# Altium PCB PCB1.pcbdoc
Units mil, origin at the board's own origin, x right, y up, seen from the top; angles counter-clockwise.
Board outline 4960.63 x 4488.19 mil, 2 copper layers (Top Layer, Bottom Layer), stack 62.206 mil thick; 33 components, 44 nets, 173 pads, 61 vias.
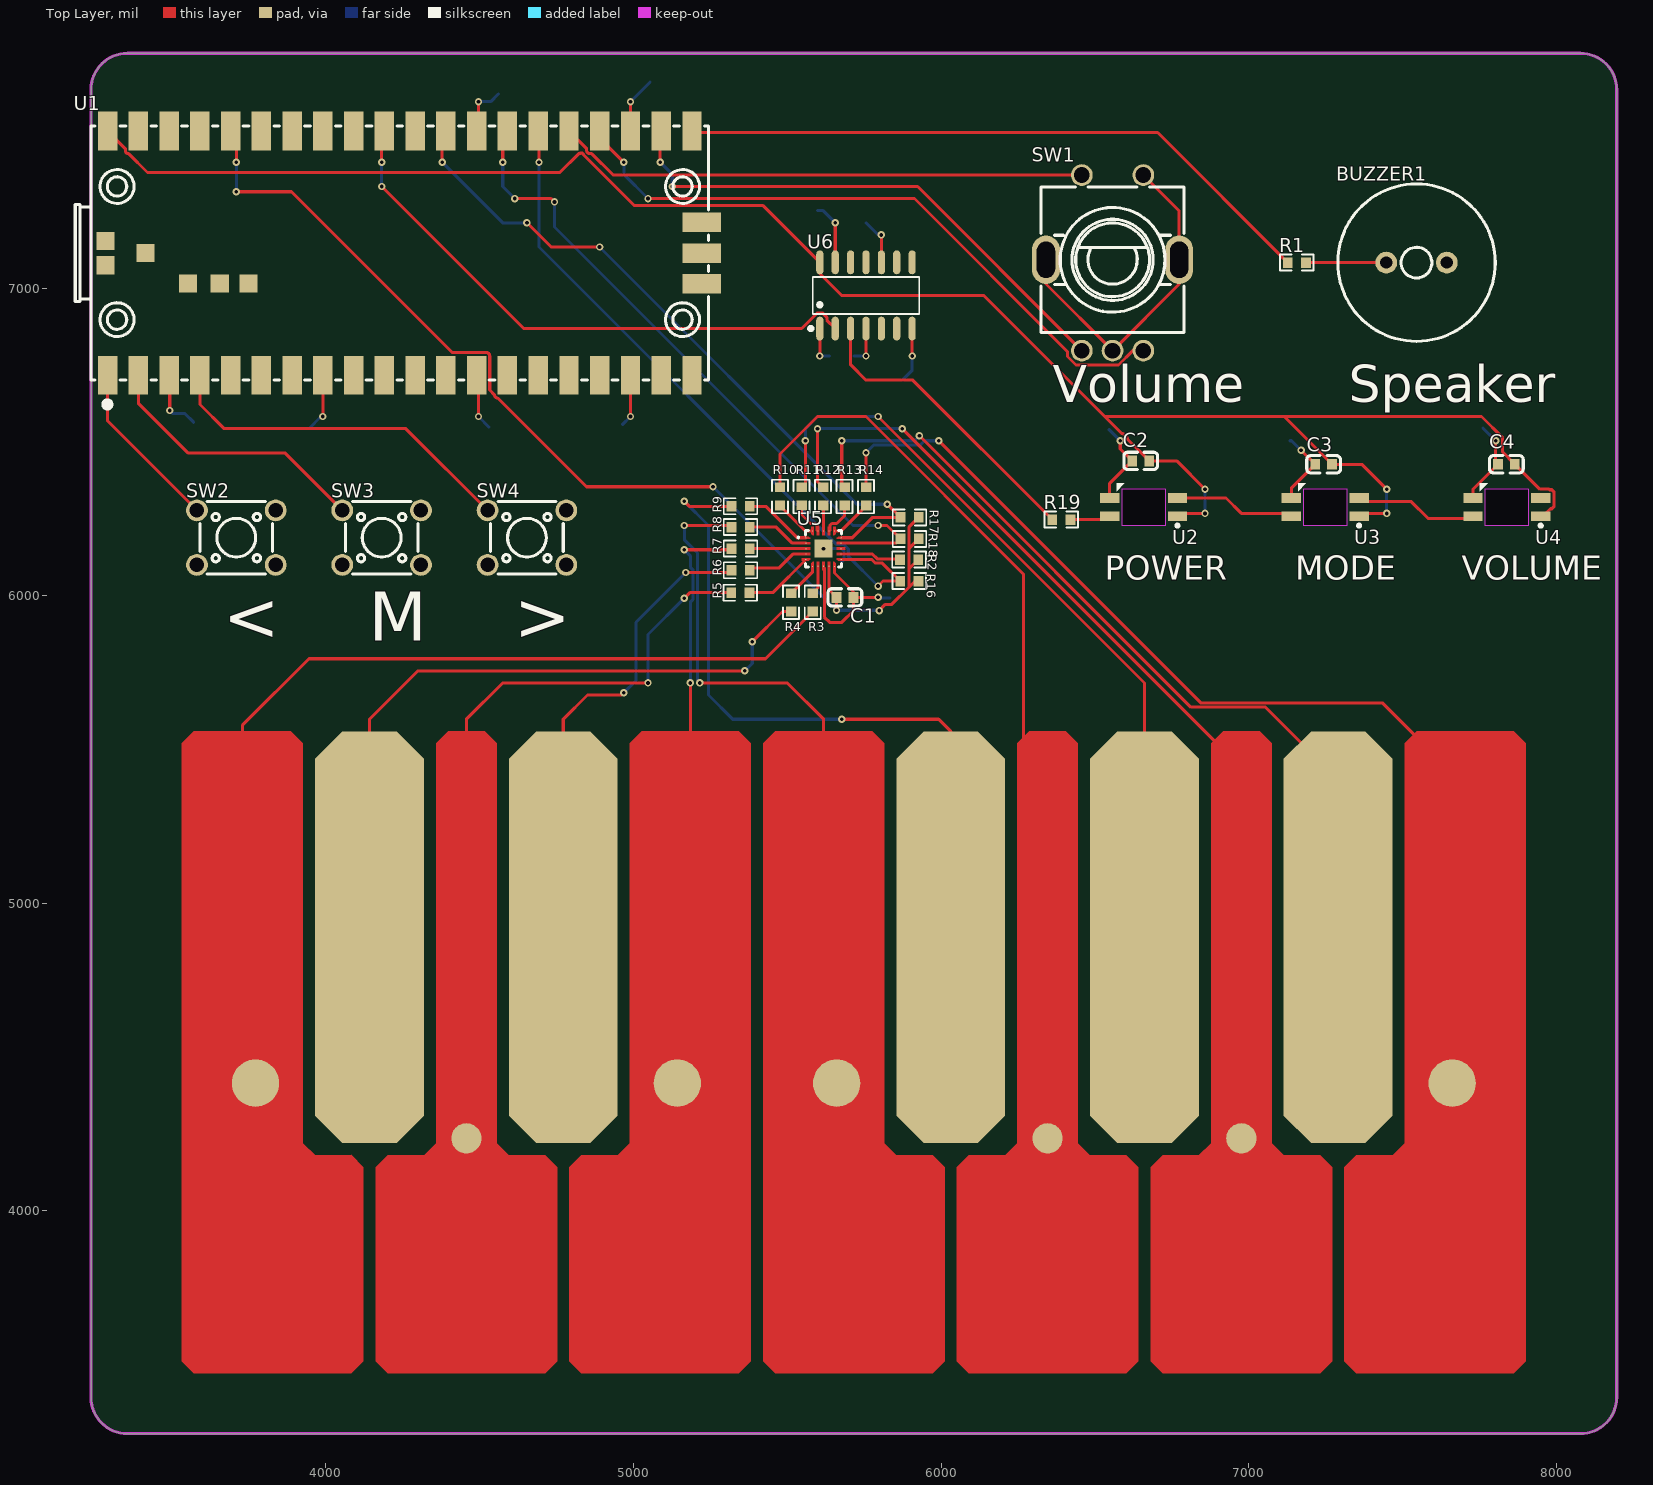
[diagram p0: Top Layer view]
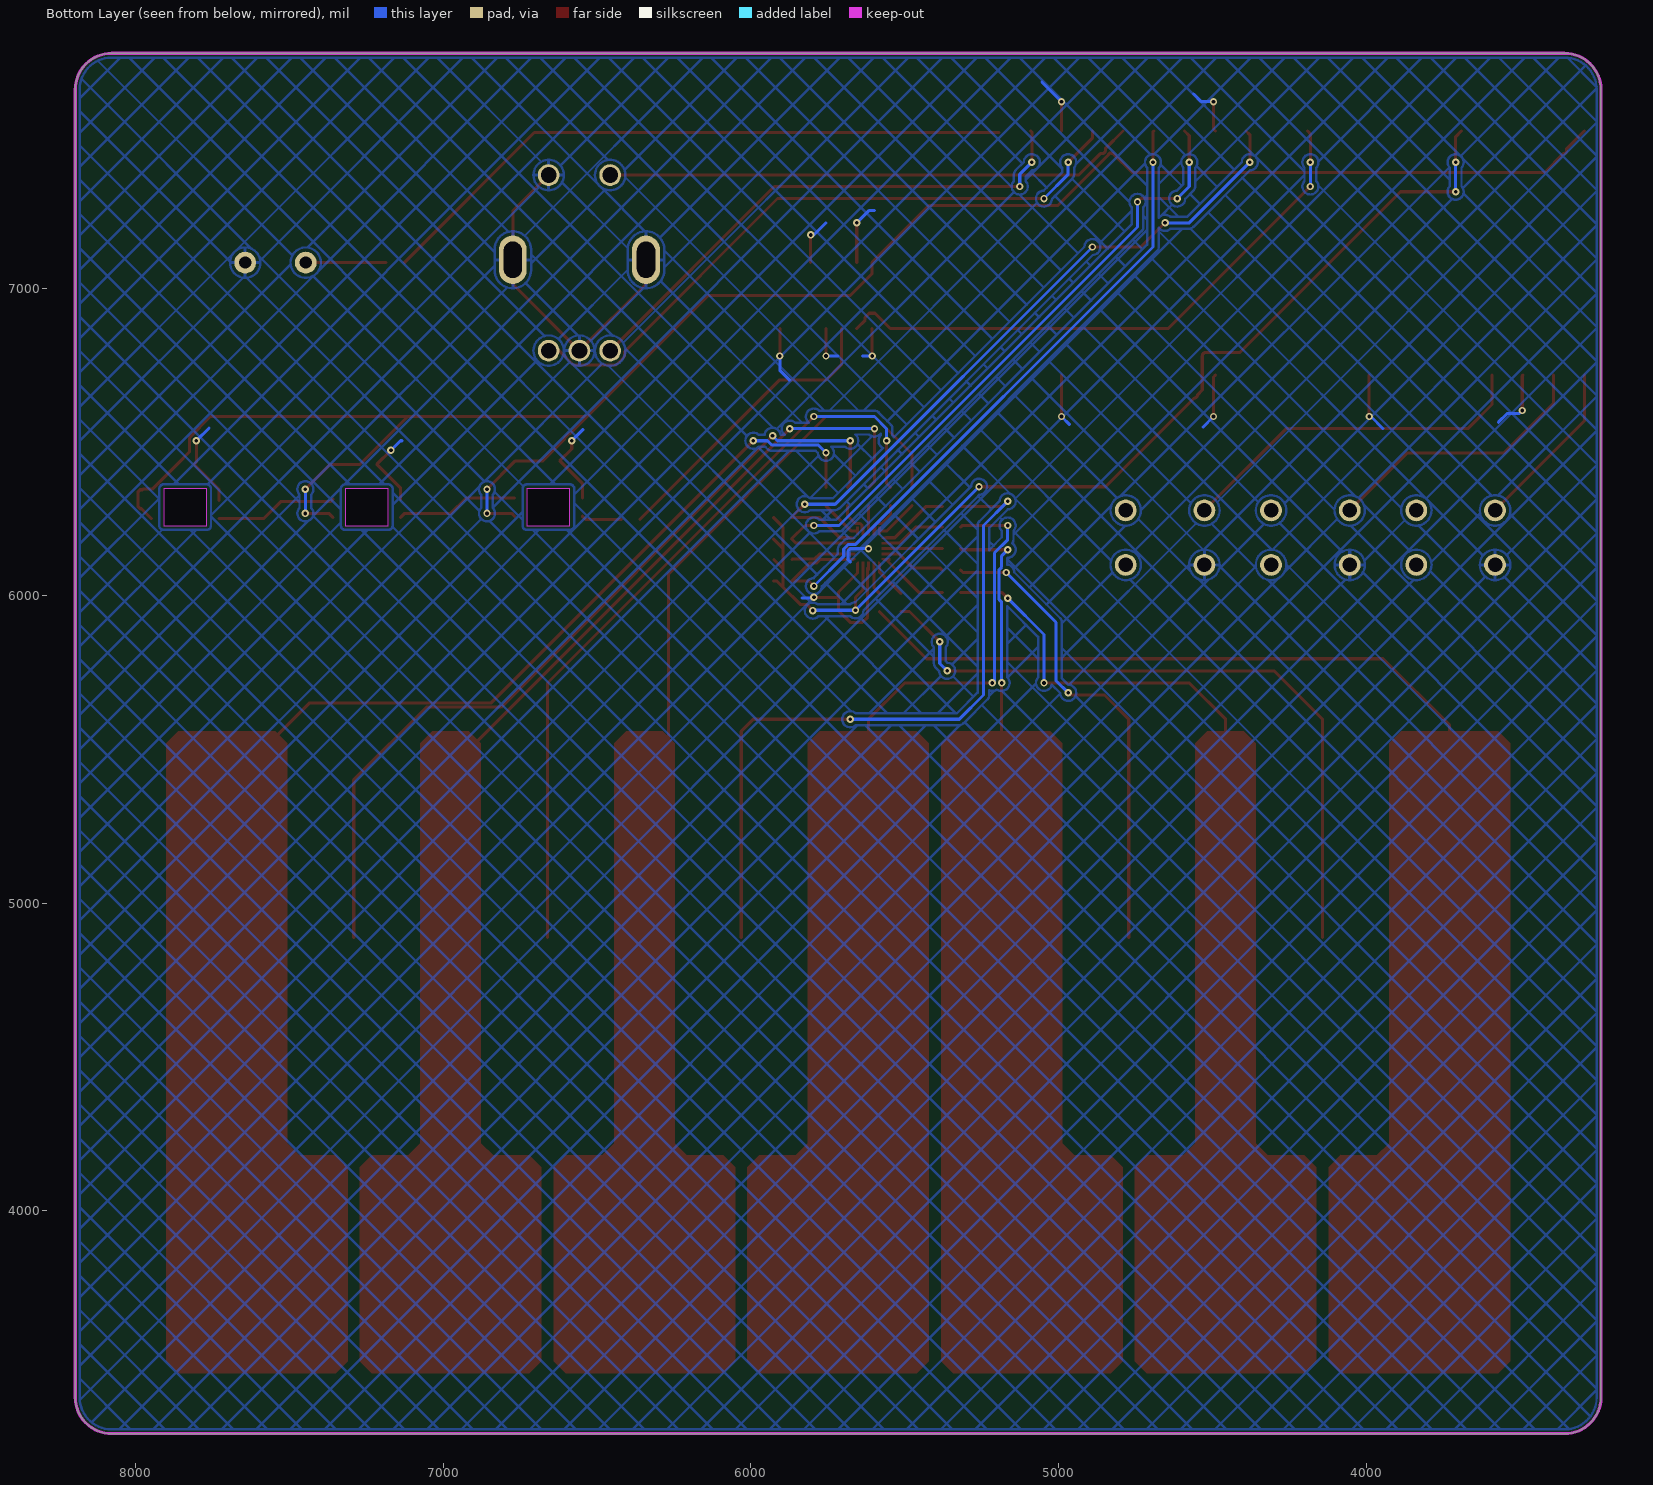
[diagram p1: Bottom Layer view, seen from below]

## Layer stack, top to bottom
Top Solder Mask Layer: solder mask 0.394, Dk 3.3
Top Layer: signal copper 1.379
Dielectric1: surface 59.449, FR4, Dk 4.5
Bottom Layer: signal copper 1.378
Bottom Solder Mask Layer: solder mask 0.394, Dk 3.3

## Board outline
3354.33,7763.78 ccw(c3354.33,7645.67) 3236.22,7645.67 3236.22,3393.7 ccw(c3354.33,3393.7) 3354.33,3275.59 8078.74,3275.59 ccw(c8078.74,3393.7) 8196.85,3393.7 8196.85,7645.67 ccw(c8078.74,7645.67) 8078.74,7763.78

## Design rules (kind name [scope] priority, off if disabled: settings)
BoardOutlineClearance copperThickness1oz [All] p0: genericclearance=10 ignorepadtopadclearanceinfootprint=FALSE except(0: Arc-SplitContinuation Track-SplitContinuation SMDPad-SplitContinuation THPad-SplitContinuation Via-SplitContinuation Fill-SplitContinuation Poly-SplitContinuation Region-SplitContinuation Text-SplitContinuation)
BoardOutlineClearance copperThickness2oz [All] p0: genericclearance=10 ignorepadtopadclearanceinfootprint=FALSE except(0: Arc-SplitContinuation Track-SplitContinuation SMDPad-SplitContinuation THPad-SplitContinuation Via-SplitContinuation Fill-SplitContinuation Poly-SplitContinuation Region-SplitContinuation Text-SplitContinuation)
BoardOutlineClearance otherClearance [All] p0: genericclearance=10 ignorepadtopadclearanceinfootprint=FALSE except(0: Arc-SplitContinuation Track-SplitContinuation SMDPad-SplitContinuation THPad-SplitContinuation Via-SplitContinuation Fill-SplitContinuation Poly-SplitContinuation Region-SplitContinuation Text-SplitContinuation)
Clearance copperThickness1oz [All] p1: gap=7 ignorepadtopadclearanceinfootprint=FALSE
Clearance copperThickness2oz [All] p1: gap=7 ignorepadtopadclearanceinfootprint=FALSE
Clearance otherClearance [All] p1: gap=7 ignorepadtopadclearanceinfootprint=FALSE
DiffPairsRouting differentialPair [All] p1: maxuncoupledlength=10 minlimit=6 maxlimit=Infinity mostfreqgap=6 toplayer_minwidth=5 toplayer_prefwidth=10 toplayer_maxwidth=100 bottomlayer_minwidth=5 bottomlayer_prefwidth=10 bottomlayer_maxwidth=100
PasteMaskExpansion pasteMaskExpansion [All] p1: expansion=0
PlaneConnect innerPlane [All] p1: planeconnectstyle=Relief reliefexpansion=20 reliefentries=4 reliefconductorwidth=10 reliefairgap=10
PolygonConnect copperRegion [All] p1: connectstyle=Relief reliefentries=4 reliefconductorwidth=10 polygonreliefangle="90 Angle" airgapwidth=10
RoutingVias viaSize [All] p1: viastyle="Through Hole" holewidth=12.0078 minholewidth=11.811 maxholewidth=248.0314 width=12.0078 minwidth=11.811 maxwidth=248.0314
SolderMaskExpansion solderMaskExpansion [IsVia] p1: useseparateexpansions=TRUE expansion=-1000 expansionbottom=-1000
SolderMaskExpansion solderMaskExpansion [All] p2: useseparateexpansions=TRUE expansion=2 expansionbottom=2
Width copperThickness1oz [All] p1: maxlimit=100 minlimit=5 preferedwidth=10
Width copperThickness2oz [All] p1: maxlimit=100 minlimit=8 preferedwidth=10

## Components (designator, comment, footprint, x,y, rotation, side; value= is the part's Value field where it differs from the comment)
BUZZER1 "4kHz" BUZ-TH_BD12.5-P5.00-D0.9 7545.92,7083.06 r0 top
C1 "100nF" C0603 5687.52,5994.88 r180 top
C2 "100nF" C0603 6648.98,6438.66 r180 top
C3 "100nF" C0603 7243.78,6427.4 r180 top
C4 "100nF" C0603 7838.16,6427.59 r180 top
R1 "220" R0603 7156.74,7083.06 r0 top
R2 "10K" R0603 5896.06,6117.7 r0 top
R3 "4.7K" R0603 5582.64,5978.44 r90 top
R4 "4.7K" R0603 5512.64,5978.44 r90 top
R5 "4.7K" R0603 5347.52,6009.88 r0 top
R6 "4.7K" R0603 5347.98,6083.1 r0 top
R7 "4.7K" R0603 5347.98,6153.1 r0 top
R8 "4.7K" R0603 5347.98,6223.1 r0 top
R9 "4.7K" R0603 5347.98,6290.8 r0 top
R10 "4.7K" R0603 5476.4,6322.76 r90 top
R11 "4.7K" R0603 5546.4,6322.76 r90 top
R12 "4.7K" R0603 5616.4,6322.76 r90 top
R13 "4.7K" R0603 5686.4,6322.76 r90 top
R14 "4.7K" R0603 5756.4,6322.76 r90 top
R16 "4.7K" R0603 5896.87,6047.7 r0 top
R17 "47K" R0603 5897.52,6254.88 r0 top
R18 "4.7K" R0603 5897.52,6184.88 r180 top
R19 "330" R0603 6390.97,6247.74 r0 top
SW1 "EC11E18244AU" SW-TH_EC11XXXXXXXX 6557.74,7082.33 r0 top
SW2 "1825910-6" SW-TH_4P-L6.0-W6.0-P4.50-LS6.5 3708.66,6188.98 r0 top
SW3 "1825910-6" SW-TH_4P-L6.0-W6.0-P4.50-LS6.5 4181.1,6188.98 r0 top
SW4 "1825910-6" SW-TH_4P-L6.0-W6.0-P4.50-LS6.5 4653.54,6188.98 r0 top
U1 "Raspberry Pi Pico 2" COMM-SMD_L51.0-W21.0-P2.54_SC0916 4252.55,7114.19 r0 top
U2 "IN-PI32TAR5R5G5B" LED-SMD_IN-PI32TARXRXGXB 6658.49,6288.06 r180 top
U3 "IN-PI32TAR5R5G5B" LED-SMD_IN-PI32TARXRXGXB 7249.04,6288.06 r180 top
U4 "IN-PI32TAR5R5G5B" LED-SMD_IN-PI32TARXRXGXB 7839.59,6288.06 r180 top
U5 "AT42QT2120-MMH" VQFN-20_L3.0-W3.0-P0.45-TL-EP 5617.88,6153.1 r0 top
U6 "74AHCT125D,118" SOP-14_L8.6-W3.9-P1.27-LS6.0-BL 5755.91,6976.38 r0 top

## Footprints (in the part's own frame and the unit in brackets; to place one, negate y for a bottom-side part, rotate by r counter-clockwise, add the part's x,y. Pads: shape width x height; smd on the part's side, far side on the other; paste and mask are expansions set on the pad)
BUZ-TH_BD12.5-P5.00-D0.9 [mm]
  round 1.8 hole 1: 1(-2.5,0) 2(2.5,0)
  silkscreen extent -6.5,-6.5 6.5,6.5
C0603 [mm]
  rect 0.8x0.9 smd: 1(-0.7,0) 2(0.7,0)
  silkscreen extent -1.39,-0.71 1.39,0.71
COMM-SMD_L51.0-W21.0-P2.54_SC0916 [mm]
  rect 1.6x3.2 smd: 1(-24.445,-10.087) 2(-21.905,-10.087) 3(-19.365,-10.087) 4(-16.825,-10.087) 5(-14.285,-10.087) 6(-11.745,-10.087) 7(-9.205,-10.087) 8(-6.665,-10.087) 9(-4.125,-10.087) 10(-1.585,-10.087) 11(0.955,-10.087) 12(3.495,-10.087) 13(6.035,-10.087) 14(8.575,-10.087) 15(11.115,-10.087) 16(13.655,-10.087) 17(16.195,-10.087) 18(18.735,-10.087) 19(21.275,-10.087) 20(23.815,-10.087) 21(23.815,10.087) 22(21.275,10.087) 23(18.735,10.087) 24(16.195,10.087) 25(13.655,10.087) 26(11.115,10.087) 27(8.575,10.087) 28(6.035,10.087) 29(3.495,10.087) 30(0.955,10.087) 31(-1.585,10.087) 32(-4.125,10.087) 33(-6.665,10.087) 34(-9.205,10.087) 35(-11.745,10.087) 36(-14.285,10.087) 37(-16.825,10.087) 38(-19.365,10.087) 39(-21.905,10.087) 40(-24.445,10.087)
  rect 3.2x1.6 smd: 41(24.615,-2.54) 42(24.615,0) 43(24.615,2.54)
  rect 1.5x1.5 smd: TP1(-21.315,0) TP2(-24.615,1) TP3(-24.615,-1) TP4(-17.815,-2.5) TP5(-15.188,-2.5) TP6(-12.815,-2.5)
  silkscreen extent -27.11,-12.75 25.18,10.5
LED-SMD_IN-PI32TARXRXGXB [mm]
  rect 1.6x0.82 smd: 1(-2.8,0.75) 2(-2.8,-0.75) 3(2.8,-0.75) 4(2.8,0.75)
  Board Outline Layer lines w0.003: 1.778,1.524 1.651,1.524 -1.651,1.524 -1.778,1.524 -1.778,-1.524 1.778,-1.524 1.778,1.524
  Board Outline Layer region: -1.651,1.524 1.651,1.524 1.778,1.524 1.778,-1.524 -1.778,-1.524 -1.778,1.524
  Board Outline Layer region: -1.651,1.524 1.651,1.524 1.778,1.524 1.778,-1.524 -1.778,-1.524 -1.778,1.524
  Multi-Layer board cut-out: -1.651,1.524 1.651,1.524 1.778,1.524 1.778,-1.524 -1.778,-1.524 -1.778,1.524
  silkscreen extent -2.92,-1.97 2.22,1.65
R0603 [mil]
  rect 31.75x34.02 smd paste-3937.01 mask+2: 1(-29.66,0) 2(29.66,0)
  silkscreen extent -55,-26 55,26
SOP-14_L8.6-W3.9-P1.27-LS6.0-BL [mm]
  oval 0.595x1.968 smd: 1(-3.81,-2.734) 2(-2.54,-2.734) 3(-1.27,-2.734) 4(0,-2.734) 5(1.27,-2.734) 6(2.54,-2.734) 7(3.81,-2.734) 8(3.81,2.734) 9(2.54,2.734) 10(1.27,2.734) 11(0,2.734) 12(-1.27,2.734) 13(-2.54,2.734) 14(-3.81,2.734)
  silkscreen extent -4.71,-2.88 4.4,1.52
SW-TH_4P-L6.0-W6.0-P4.50-LS6.5 [mm]
  round 1.8 hole 1.2: 1(-3.25,2.25) 2(3.25,2.25) 3(-3.25,-2.25) 4(3.25,-2.25)
  silkscreen extent -3,-3 3,3
SW-TH_EC11XXXXXXXX [mm]
  oval 2.3x4 hole 1.5 slot 3 at 90 deg: 6(5.5,0.25) 7(-5.5,0.25)
  round 1.8 hole 1.3: A(-2.54,-7.25) B(2.54,-7.25) C(0,-7.25) D(-2.54,7.25) E(2.54,7.25)
  silkscreen extent -5.9,-5.75 5.9,6.25
VQFN-20_L3.0-W3.0-P0.45-TL-EP [mm]
  round 0.098 smd: 1(-1.462,0.898) 5(-1.462,-0.898) 6(-0.898,-1.462) 11(1.462,-0.897) 16(0.898,1.462) 20(-0.898,1.462)
  round 0.1 smd: 2(-1.45,0.45) 3(-1.45,0) 4(-1.45,-0.45) 7(-0.45,-1.45) 8(0,-1.45) 9(0.45,-1.45) 12(1.45,-0.45) 13(1.45,0) 14(1.45,0.45) 17(0.45,1.45) 18(0,1.45) 19(-0.45,1.45)
  round 0.097 smd: 10(0.898,-1.462) 15(1.462,0.898)
  rect 1.5x1.5 smd paste-100 mask+0.05: 21(0,0)
  Top Layer region: 0.55,-1.7 0.55,-1.8 0.35,-1.8 0.35,-1.1 0.55,-1.1
  Top Layer region: -0.8,-1.1 -0.8,-1.8 -1,-1.8 -1,-1.25 -1,-1.2 -0.9,-1.1
  Top Layer region: -1.1,0.8 -1.8,0.8 -1.8,1 -1.25,1 -1.2,1 -1.1,0.9
  Top Layer region: 1.1,0.8 1.8,0.8 1.8,1 1.25,1 1.2,1 1.1,0.9
  Top Layer region: 0.8,1.1 0.8,1.8 1,1.8 1,1.25 1,1.2 0.9,1.1
  Top Layer region: 0.8,-1.1 0.8,-1.8 1,-1.8 1,-1.25 1,-1.2 0.9,-1.1
  Top Layer region: 1.1,-0.8 1.8,-0.8 1.8,-1 1.25,-1 1.2,-1 1.1,-0.9
  Top Layer region: 0.1,1.2 0.1,1.1 -0.1,1.1 -0.1,1.8 0.1,1.8
  Top Layer region: 0.55,1.2 0.55,1.1 0.35,1.1 0.35,1.8 0.55,1.8
  Top Layer region: 1.2,0.35 1.1,0.35 1.1,0.55 1.8,0.55 1.8,0.35
  Top Layer region: 1.2,-0.1 1.1,-0.1 1.1,0.1 1.8,0.1 1.8,-0.1
  Top Layer region: 1.2,-0.55 1.1,-0.55 1.1,-0.35 1.8,-0.35 1.8,-0.55
  Top Layer region: -1.2,0.35 -1.1,0.35 -1.1,0.55 -1.8,0.55 -1.8,0.35
  Top Layer region: -1.2,-0.1 -1.1,-0.1 -1.1,0.1 -1.8,0.1 -1.8,-0.1
  Top Layer region: -1.2,-0.55 -1.1,-0.55 -1.1,-0.35 -1.8,-0.35 -1.8,-0.55
  Top Layer region: -1.1,-0.8 -1.8,-0.8 -1.8,-1 -1.25,-1 -1.2,-1 -1.1,-0.9
  Top Layer region: -0.55,-1.7 -0.55,-1.8 -0.35,-1.8 -0.35,-1.1 -0.55,-1.1
  Top Layer region: -0.1,-1.7 -0.1,-1.8 0.1,-1.8 0.1,-1.1 -0.1,-1.1
  Top Layer region: -0.55,1.2 -0.55,1.1 -0.35,1.1 -0.35,1.8 -0.55,1.8
  Top Layer region: -0.8,1.1 -0.8,1.8 -1,1.8 -1,1.25 -1,1.2 -0.9,1.1
  silkscreen extent -2.15,-1.5 1.5,1.5

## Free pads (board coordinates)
  round 154.13 smd: 0(3771.07,4415.42)
  oct 354.33x1338.58 smd: 1(4141.73,4889.76) 3(4771.65,4889.76) 6(6031.5,4889.76) 8(6661.42,4889.76) 10(7291.34,4889.76)
  round 98.43 smd: 2(4456.69,4235.86) 7(6346.46,4235.86) 9(6976.38,4235.86)
  round 154.15 smd: 4(5142.34,4415.43) 5(5660.81,4415.43) 11(7662.02,4415.43)

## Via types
v1: diameter 24.02, hole 12, Top Layer to Bottom Layer, 61 vias

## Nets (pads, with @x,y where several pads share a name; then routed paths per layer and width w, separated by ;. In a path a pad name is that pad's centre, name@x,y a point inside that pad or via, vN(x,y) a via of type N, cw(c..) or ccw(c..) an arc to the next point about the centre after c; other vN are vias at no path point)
$1N51: BUZZER1.1 R1.2 | length 261.1
  Top Layer w10: R1.2 BUZZER1.1
$1N69: R3.2 U5.7 | length 95.2
  Top Layer w10: R3.2 5600.17,6025.63 U5.7
$1N70: R4.2 U5.6 | length 116.8
  Top Layer w10: R4.2 5582.45,6077.91 U5.6@5582.45,6096.01
$1N71: R5.2 U5.5 | length 228.3
  Top Layer w10: R5.2 5453,6009.88 U5.5@5560.79,6117.67
$1N72: R6.2 U5.4 | length 204.8
  Top Layer w10: R6.2 5384.42,6089.88 5472.52,6089.88 5518.03,6135.39 U5.4
$1N73: R7.2 U5.3 | length 183.2
  Top Layer w10: R7.2 U5.3
$1N74: R8.2 U5.2 | length 204.8
  Top Layer w10: R8.2 5464.3,6223.1 5516.58,6170.82 U5.2
$1N75: R9.2 U5.1 | length 225.5
  Top Layer w10: R9.2 5430.26,6290.8 5532.52,6188.54 U5.1@5560.79,6188.54
$1N76: R14.1 U5.16 | length 137.4
  Top Layer w10: U5.16@5653.31,6210.19 5673.49,6210.19 R14.1
$1N77: R2.1 U5.12 | length 198.8
  Top Layer w10: U5.12 5777.01,6135.39 5792.52,6119.88 5864.22,6119.88 R2.1
$1N78: R13.1 U5.17 | length 113.1
  Top Layer w10: U5.17 5638.39,6212.98 5638.39,6228.52 5644.82,6234.95 5660.36,6234.95 5686.4,6261 R13.1
$1N79: R12.1 U5.18 | length 83.5
  Top Layer w10: R12.1 5617.88,6291.63 U5.18
$1N80: R11.1 U5.19 | length 114.3
  Top Layer w10: R11.1 5546.4,6263.95 5575.39,6234.96 5590.93,6234.96 5597.36,6228.52 5597.36,6212.99 U5.19
$1N81: R10.1 U5.20 | length 140.4
  Top Layer w10: R10.1 5559.32,6210.19 U5.20@5582.45,6210.19
$1N114: R19.2 U2.4 | length 132.1
  Top Layer w10: R19.2 6537.47,6247.74 U2.4
$1N133: U2.2 U3.4 | length 396.1
  Top Layer w10: U2.2 6926.51,6317.59 6976.38,6267.72 7125.81,6267.72 U3.4@7138.8,6254.73
$1N134: U3.2 U4.4 | length 396.1
  Top Layer w10: U3.2@7359.28,6313.79 7365.98,6307.09 7527.56,6307.09 7583.72,6250.93 U4.4@7729.35,6250.93
CTS_CHANGE: R17.1 U1.29 U5.15 | length 2295.4
  Top Layer w10: v1(4377.95,7409.45) 4377.95,7499.14 U1.29 ; v1(4653.54,7212.6) 4732.28,7133.86 v1(4889.76,7133.86) ; U5.15@5674.97,6188.54 5711.18,6188.54 5777.52,6254.88 R17.1 v1(5825.16,6297.58)
  Bottom Layer w10: v1(4377.95,7409.45) 4574.8,7212.6 v1(4653.54,7212.6) ; v1(4889.76,7133.86) 5726.04,6297.58 v1(5825.16,6297.58)
CTS_PWR: C1.2 R2.2 R16.2 R17.2 R18.1 U1.36 U5.9 | length 3573.2
  Top Layer w10: U1.36 3708.66,7492.81 v1(3708.66,7409.45) ; v1(3708.66,7313.64) 3887.84,7313.64 4410.45,6791.03 4521.64,6791.03 cw(c4521.64,6780.04) 4532.63,6780.04 4532.63,6668.85 4547.67,6653.81 ccw(c4558.65,6654.06) 4558.4,6643.08 4847.09,6354.38 v1(5258.33,6354.38) ; U5.9 5635.6,6019.24 C1.2 v1(5659.96,5952.76) ; v1(5798.72,5951.79) 5818.82,5971.89 5839.82,5971.89 5896.35,6028.42 ; R2.2 5896.35,6088.32 ; R16.2 5915.63,6047.7 5896.35,6028.42 ; R18.1 5896.35,6154.05 ; R17.2 5896.35,6224.05 5896.35,6154.05 ; 5896.35,6028.42 5896.35,6088.32 ; 5896.35,6088.32 5896.35,6154.05
  Bottom Layer w10: v1(3708.66,7313.64) v1(3708.66,7409.45) ; v1(5258.33,6354.38) v1(5659.96,5952.76) 5797.76,5952.76 v1(5798.72,5951.79)
CTS_SCL: R18.2 U1.27 U5.14 | length 2201
  Top Layer w10: v1(4574.8,7409.45) 4574.8,7495.99 U1.27 ; v1(4614.17,7291.34) 4732.28,7291.34 v1(4743.17,7280.45) ; U5.14 5853.8,6170.82 R18.2 5824.4,6228.35 v1(5795.28,6228.35)
  Bottom Layer w10: v1(4574.8,7409.45) 4574.8,7330.71 v1(4614.17,7291.34) ; v1(4743.17,7280.45) 4743.17,7199.1 5713.93,6228.35 v1(5795.28,6228.35)
CTS_SDA: R16.1 U1.26 U5.11 | length 2251.1
  Top Layer w10: U1.26 4692.91,7508.56 v1(4692.91,7409.45) ; U5.11@5674.97,6117.67 5774.91,6117.67 5786.71,6105.87 5809.04,6105.87 R16.1 5811.48,6047.7 v1(5795.28,6031.5)
  Bottom Layer w10: v1(4692.91,7409.45) 4692.91,7133.86 5659.65,6167.12 5682.97,6167.12 5698.25,6151.84 5698.25,6128.52 v1(5795.28,6031.5)
GND: BUZZER1.2 C1.1 C2.2 C3.2 C4.2 SW1.6 SW1.7 SW1.C SW1.E SW2.3 SW3.3 SW4.3 U1.3 U1.8 U1.13 U1.18 U1.23 U1.28 U2.3 U3.3 U4.3 U5.8 U5.10 U5.21 U6.1 U6.4 U6.7 U6.10 U6.13 | length 4517
  Top Layer w10: U1.3 3492.13,6715.07 v1(3492.13,6602.36) ; v1(3990.15,6582.68) U1.8 ; U1.13 4496.06,6711.13 v1(4496.06,6582.68) ; U1.28 4496.06,7517.25 v1(4496.06,7606.3) ; v1(4990.15,6582.68) U1.18 ; U1.23 v1(4990.15,7606.3) ; v1(5605.91,6779.53) U6.1 ; U5.8 5617.88,6092.08 5620.67,6089.29 5620.67,5930.51 5637.8,5913.39 5677.17,5913.39 5715.08,5951.3 C1.1 ; U5.10@5653.31,6096.02 5653.31,6074.09 5715.08,6012.32 C1.1 ; U6.13 v1(5655.91,7212.6) ; v1(5755.91,6779.53) U6.4 ; v1(5795.28,5994.88) C1.1 ; U6.10 v1(5805.91,7173.23) ; v1(5905.91,6779.53) U6.7 ; SW1.7 6341.21,7013.42 SW1.C 6774.28,7013.43 SW1.6 6774.28,7251.22 SW1.E ; U2.3 6548.25,6365.5 C2.2 6582.68,6477.4 v1(6582.68,6503.94) ; U3.3@7138.8,6313.79 7138.8,6349.99 C3.2 v1(7170.53,6473.09) ; U4.3@7729.35,6309.99 7729.35,6346.35 C4.2 7803.15,6435.04 v1(7803.15,6503.94)
  Bottom Layer w10: v1(3492.13,6602.36) 3501.97,6592.52 3541.34,6592.52 3569.91,6563.95 ; 3944.88,6543.31 3984.25,6582.68 v1(3990.15,6582.68) ; v1(4496.06,6582.68) 4530.48,6548.26 ; v1(4496.06,7606.3) 4535.43,7606.3 4560.77,7631.64 ; 4963.8,6556.33 v1(4990.15,6582.68) ; v1(4990.15,7606.3) 5053.8,7669.96 ; 5598.43,7251.97 5616.54,7251.97 v1(5655.91,7212.6) ; v1(5605.91,6779.53) 5637.8,6779.53 ; v1(5617.88,6153.1) 5677.17,6153.1 5684.24,6146.03 5684.24,6117.31 5677.17,6110.24 ; 5716.54,6779.53 v1(5755.91,6779.53) ; 5755.91,7212.6 5795.28,7173.23 v1(5805.91,7173.23) ; v1(5795.28,5994.88) 5798.03,5992.13 5834.65,5992.13 ; 5874.02,6700.79 5905.91,6732.68 v1(5905.91,6779.53) ; 6546.89,6539.73 v1(6582.68,6503.94) ; 7133.86,6503.94 7139.68,6503.94 v1(7170.53,6473.09) ; 7762.25,6544.84 v1(7803.15,6503.94)
LED_DATA: R19.1 U6.3 | length 981.7
  Top Layer w10: U6.3 5705.91,6750.79 5755.91,6700.79 5908.26,6700.79 R19.1
LED_PWR: C2.1 C3.1 C4.1 U1.40 U2.1 U3.1 U4.1 U6.14 | length 6603.7
  Top Layer w10: U1.40 3347.67,7453.81 3347.67,7448.34 ccw(c3358.65,7448.34) 3358.65,7437.35 3420.01,7376 4760.28,7376 4821.64,7437.35 ccw(c4821.64,7448.34) 4827.72,7439.19 4833.65,7439.19 4837,7435.84 4837,7434.63 5003.29,7268.35 5421.57,7268.35 U6.14 5605.91,7047.64 5677.17,6976.38 6138.82,6976.38 6532.52,6582.68 ; U2.1 6777.92,6267.72 v1(6858.27,6267.72) ; v1(6858.27,6346.46) 6766.06,6438.66 C2.1 6605.67,6509.53 6605.67,6513.46 6592.2,6526.93 6588.27,6526.93 6532.52,6582.68 ; U3.1@7359.28,6254.73 7372.27,6267.72 v1(7448.82,6267.72) ; v1(7448.82,6346.46) 7367.87,6427.4 C3.1 7116.06,6582.68 ; U4.1@7949.83,6250.93 7981.77,6282.86 7985.88,6282.86 7992.32,6289.29 7992.32,6338.28 7985.88,6344.71 7978.28,6344.71 7976.54,6346.46 7946.86,6346.46 C4.1 7826.14,6467.17 7826.14,6513.46 7756.93,6582.68 7116.06,6582.68 ; 6532.52,6582.68 7116.06,6582.68
  Bottom Layer w10: v1(6858.27,6267.72) v1(6858.27,6346.46) ; v1(7448.82,6267.72) v1(7448.82,6346.46)
PAD0: pad.0 R3.1 | length 3070.6
  Top Layer w10: 3728.35,4515.75 3728.35,5578.74 3944.88,5795.28 5429.13,5795.28 R3.1
PAD1: pad.1 R4.1 | length 2265.9
  Top Layer w10: pad.1 4141.73,5598.43 4299.21,5755.91 v1(5362.2,5755.91) ; v1(5386.06,5850.16) 5484.67,5948.78 R4.1
  Bottom Layer w10: v1(5362.2,5755.91) 5386.06,5779.76 v1(5386.06,5850.16)
PAD2: pad.2 R5.1 | length 2206.5
  Top Layer w10: 4456.69,4515.75 4456.69,5598.43 4574.8,5716.54 v1(5047.24,5716.54) ; v1(5165.35,5992.13) 5183.11,6009.88 R5.1
  Bottom Layer w10: v1(5047.24,5716.54) 5047.24,5874.02 v1(5165.35,5992.13)
PAD3: pad.3 R6.1 | length 1567.3
  Top Layer w10: pad.3 4771.65,5598.43 4850.39,5677.17 4961.43,5677.17 v1(4968.5,5684.24) ; v1(5170,6075.52) 5310.73,6075.52 R6.1
  Bottom Layer w10: v1(4968.5,5684.24) 5007.87,5723.61 5007.87,5913.39 v1(5170,6075.52)
PAD4: pad.4 R7.1 | length 1803
  Top Layer w10: v1(5165.35,6149.61) 5314.82,6149.61 R7.1 ; 5185.04,4515.75 v1(5185.04,5716.54)
  Bottom Layer w10: v1(5165.35,6149.61) 5185.04,6129.92 5185.04,6093 5193,6085.04 5193,5987.25 5185.04,5979.3 v1(5185.04,5716.54)
PAD5: pad.5 R8.1 | length 2222.2
  Top Layer w10: v1(5165.35,6228.35) 5313.07,6228.35 R8.1 ; v1(5215.04,5716.54) 5500,5716.54 5618.11,5598.43 5618.11,4515.75
  Bottom Layer w10: v1(5165.35,6228.35) 5165.35,6182.12 5208.03,6139.44 5208.03,5723.54 v1(5215.04,5716.54)
PAD6: pad.6 R9.1 | length 2327.9
  Top Layer w10: v1(5165.35,6307.09) 5181.64,6290.8 R9.1 ; v1(5677.17,5598.43) 5992.13,5598.43 6031.5,5559.06 pad.6
  Bottom Layer w10: v1(5165.35,6307.09) 5244.09,6228.35 5244.09,5677.17 5322.83,5598.43 v1(5677.17,5598.43)
PAD7: pad.7 R10.2 | length 2749.8
  Top Layer w10: R10.2 5476.4,6460.66 5598.43,6582.68 5755.91,6582.68 6267.72,6070.87 6267.72,4594.49 6346.46,4515.75
PAD8: pad.8 R11.2 | length 2500.3
  Top Layer w10: R11.2 5559.06,6365.07 v1(5559.06,6503.94) ; v1(5795.28,6582.68) 6661.42,5716.54 pad.8
  Bottom Layer w10: v1(5559.06,6503.94) 5559.06,6543.31 5598.43,6582.68 v1(5795.28,6582.68)
PAD9: pad.9 R12.2 | length 2958.1
  Top Layer w10: v1(5598.43,6543.31) 5598.43,6370.4 R12.2 ; v1(5874.02,6543.31) 6976.38,5440.94 6976.38,4515.75
  Bottom Layer w10: v1(5598.43,6543.31) v1(5874.02,6543.31)
PAD10: pad.10 R13.2 | length 2751.4
  Top Layer w10: v1(5677.17,6503.94) 5677.17,6361.66 R13.2 ; v1(5929.64,6520.19) 6812.04,5637.8 7055.12,5637.8 7291.34,5401.57 pad.10
  Bottom Layer w10: v1(5677.17,6503.94) 5913.39,6503.94 v1(5929.64,6520.19)
PAD11: pad.11 R14.2 | length 3408.4
  Top Layer w10: v1(5755.91,6464.57) 5756.4,6464.07 R14.2 ; v1(5992.13,6503.94) 6844.25,5651.81 7434.8,5651.81 7704.72,5381.89 7704.72,4515.75
  Bottom Layer w10: v1(5755.91,6464.57) 5781.26,6489.92 5931.89,6489.92 5945.9,6503.94 v1(5992.13,6503.94)
ROT_A: SW1.A U1.22 | length 1751.3
  Top Layer w10: v1(5086.61,7409.45) 5086.61,7507.8 U1.22 ; v1(5125.98,7330.71) 5923.92,7330.71 SW1.A
  Bottom Layer w10: v1(5086.61,7409.45) 5125.98,7370.08 v1(5125.98,7330.71)
ROT_B: SW1.B U1.24 | length 2148
  Top Layer w10: U1.24 4890.15,7487.81 v1(4968.5,7409.45) ; v1(5047.24,7291.34) 5913.39,7291.34 6411.32,6793.41 6411.32,6777.66 6438.51,6750.47 6576.96,6750.47 6623.38,6796.89 SW1.B
  Bottom Layer w10: v1(4968.5,7409.45) 4968.5,7370.08 v1(5047.24,7291.34)
ROT_D: SW1.D U1.25 | length 1732
  Top Layer w10: U1.25 4847.67,7453.81 4847.67,7448.34 ccw(c4858.65,7448.34) 4858.65,7437.35 4864.12,7437.35 4933.71,7367.76 SW1.D
SHIFT_DATA: U1.31 U6.2 | length 1897
  Top Layer w10: v1(4181.1,7330.71) 4643.06,6868.75 5546.79,6868.75 5596.5,6918.46 5615.31,6918.46 5628.6,6905.17 5628.6,6896.05 U6.2 ; v1(4181.1,7409.45) 4181.1,7502.29 U1.31
  Bottom Layer w10: v1(4181.1,7330.71) v1(4181.1,7409.45)
SPK_DATA: R1.1 U1.21 | length 2108.9
  Top Layer w10: U1.21@5193.34,7506.04 6704.1,7506.04 R1.1
SW0: SW2.1 U1.1 | length 559.9
  Top Layer w10: U1.1 3290.15,6568.12 SW2.1
SW1: SW3.1 U1.2 | length 898.6
  Top Layer w10: U1.2 3390.15,6625.6 3551.18,6464.57 3866.14,6464.57 SW3.1@4053.15,6277.56
SW2: SW4.1 U1.4 | length 1172.9
  Top Layer w10: U1.4 3590.55,6716.64 3590.55,6622.05 3669.29,6543.31 4259.84,6543.31 SW4.1
pads on no net: SW2.2 SW2.4 SW3.2 SW3.4 SW4.2 SW4.4 U1.5 U1.6 U1.7 U1.9 U1.10 U1.11 U1.12 U1.14 U1.15 U1.16 U1.17 U1.19 U1.20 U1.30 U1.32 U1.33 U1.34 U1.35 U1.37 U1.38 U1.39 U1.41 U1.42 U1.43 U1.TP1 U1.TP2 U1.TP3 U1.TP4 U1.TP5 U1.TP6 U4.2 U5.13 U6.5 U6.6 U6.8 U6.9 U6.11 U6.12

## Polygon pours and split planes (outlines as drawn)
GND on Bottom Layer (hatched 45Degree grid 70.8661 track 7.874, remove dead copper, pour order 0): 3000,7960.63 3000,3000 8590.55,3000 8590.55,7960.63

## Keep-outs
Board Outline Layer:
  the board outline again, w10

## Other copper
Top Layer:
  region net PAD0: 4122.05,4141.73 4122.05,3511.81 4082.68,3472.44 3570.87,3472.44 3531.5,3511.81 3531.5,5519.69 3570.87,5559.06 3885.83,5559.06 3925.2,5519.69 3925.2,4220.47 3964.57,4181.1 4081.6,4182.18
  region net PAD2: 4751.97,3511.81 4712.6,3472.44 4200.79,3472.44 4161.42,3511.81 4161.42,4141.73 4200.79,4181.1 4318.9,4181.1 4358.27,4220.47 4358.27,5519.69 4397.64,5559.06 4515.75,5559.06 4555.12,5519.69 4555.12,4220.47 4594.49,4181.1 4712.6,4181.1 4751.97,4141.73
  region net PAD4: 4791.34,3511.81 4791.34,4141.73 4830.71,4181.1 4948.82,4181.1 4988.19,4220.47 4988.19,5519.69 5027.56,5559.06 5342.52,5559.06 5381.89,5519.69 5381.89,3511.81 5342.52,3472.44 4830.71,3472.44
  region net PAD5: 5421.26,3511.81 5421.26,5519.69 5460.63,5559.06 5775.59,5559.06 5814.96,5519.69 5814.96,4220.47 5854.33,4181.1 5972.44,4181.1 6011.81,4141.73 6011.81,3511.81 5972.44,3472.44 5460.63,3472.44
  region net PAD7: 6051.18,3511.81 6051.18,4141.73 6090.55,4181.1 6208.66,4181.1 6248.03,4220.47 6248.03,5519.69 6287.4,5559.06 6405.51,5559.06 6444.88,5519.69 6444.88,4220.47 6484.25,4181.1 6602.36,4181.1 6641.73,4141.73 6641.73,3511.81 6602.36,3472.44 6090.55,3472.44
  region net PAD9: 6681.1,3511.81 6681.1,4141.73 6720.47,4181.1 6838.58,4181.1 6877.95,4220.47 6877.95,5519.69 6917.32,5559.06 7035.43,5559.06 7074.8,5519.69 7074.8,4220.47 7114.17,4181.1 7232.28,4181.1 7271.65,4141.73 7271.65,3511.81 7232.28,3472.44 6720.47,3472.44
  region net PAD11: 7311.02,3511.81 7311.02,4141.73 7350.39,4181.1 7468.5,4181.1 7507.87,4220.47 7507.87,5519.69 7547.24,5559.06 7862.2,5559.06 7901.57,5519.69 7901.57,3511.81 7862.2,3472.44 7350.39,3472.44

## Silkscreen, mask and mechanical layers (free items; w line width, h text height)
Top Silkscreen Layer:
  text "Volume" at 6362.97,6629.36 h120
  text "Speaker" at 7325.76,6629.36 h120
  text "POWER" at 6532.19,6051.84 h78.74
  text "MODE" at 7151.9,6051.84 h78.74
  text "VOLUME" at 7692.9,6051.84 h78.74
  text "<" at 3666.66,5853.07 h160
  text "M" at 4139.1,5853.07 h160
  text ">" at 4611.54,5853.07 h160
